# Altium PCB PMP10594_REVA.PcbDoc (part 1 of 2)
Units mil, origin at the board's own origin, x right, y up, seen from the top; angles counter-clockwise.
Board outline 4300 x 2600 mil, 4 copper layers (Top Layer, Signal Layer 1, Signal Layer 2, Bottom Layer), stack 61.2 mil thick; 149 components, 76 nets, 349 pads, 143 vias.
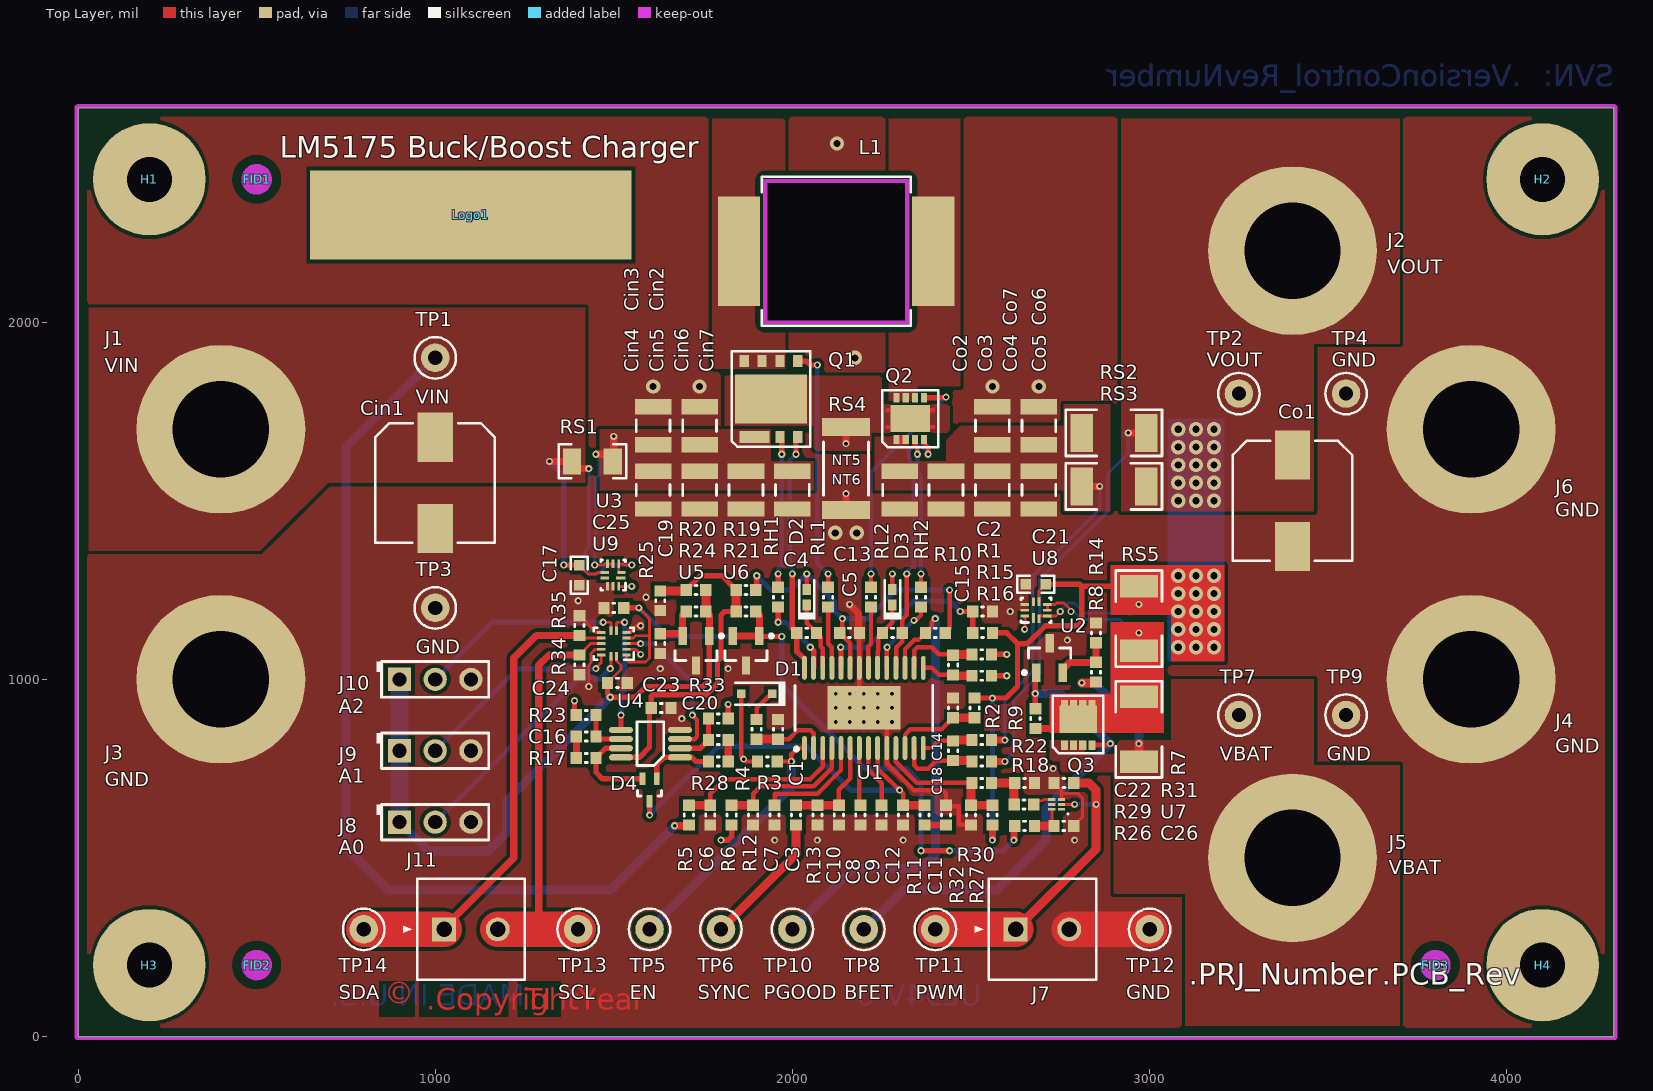
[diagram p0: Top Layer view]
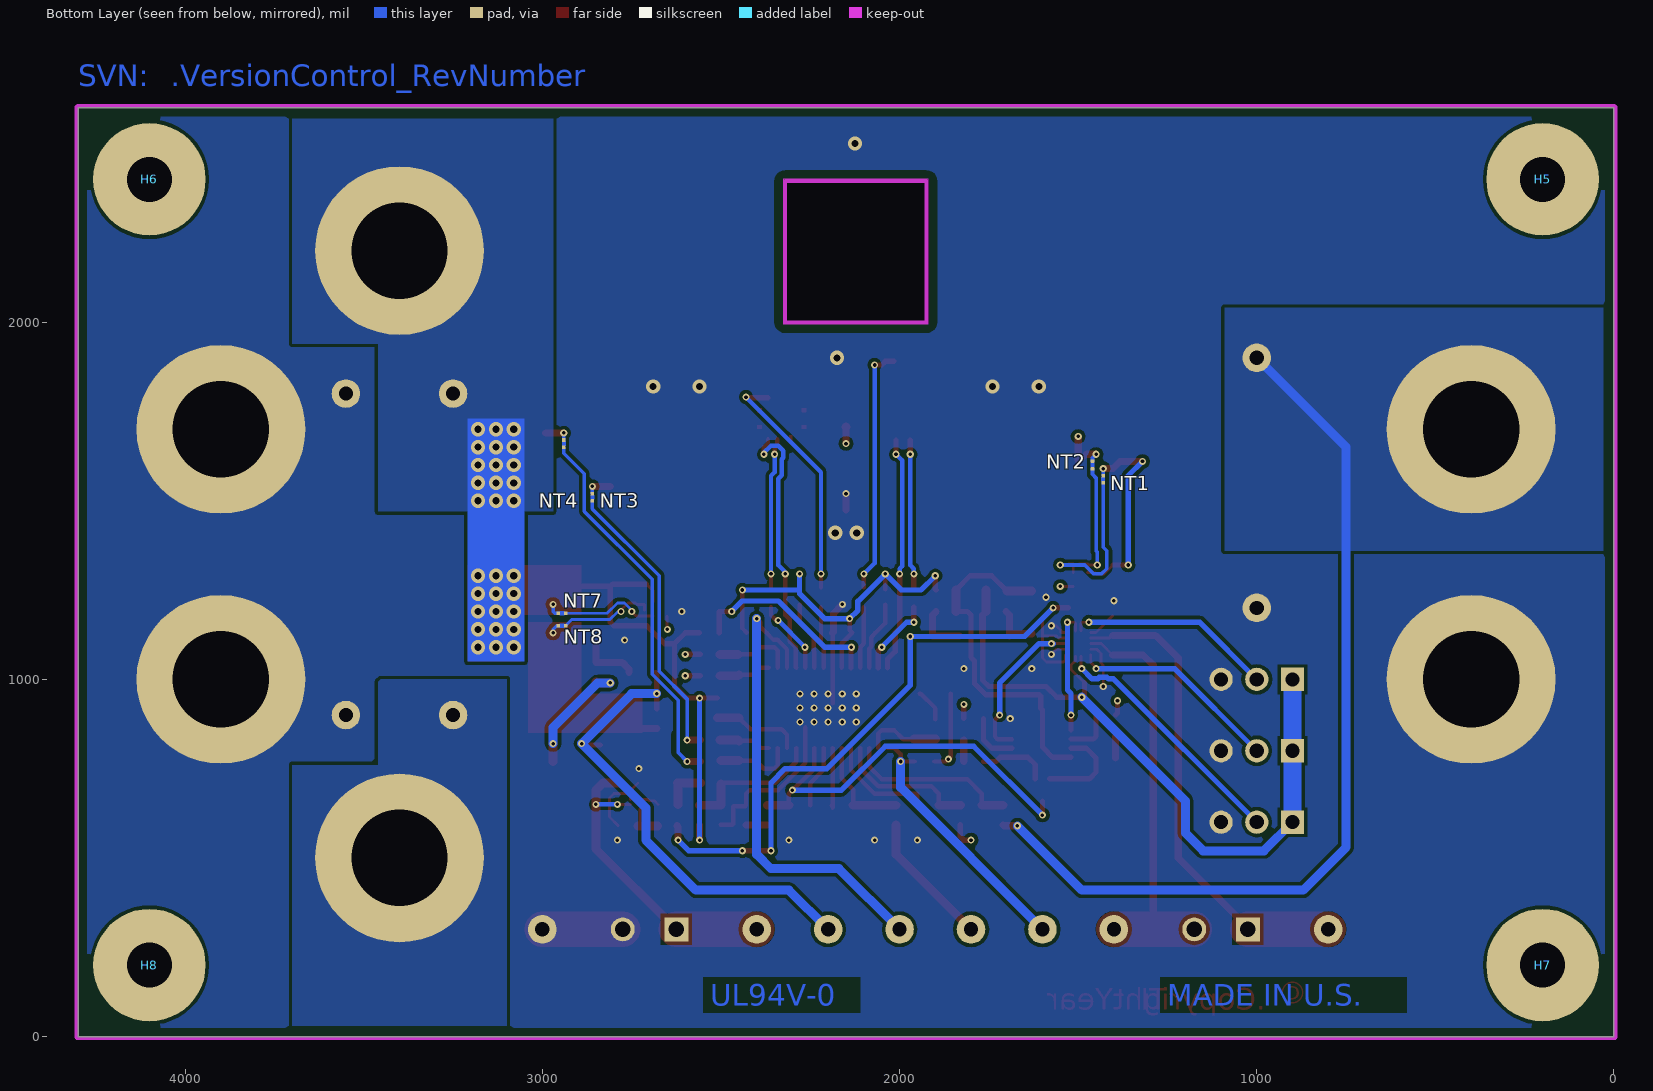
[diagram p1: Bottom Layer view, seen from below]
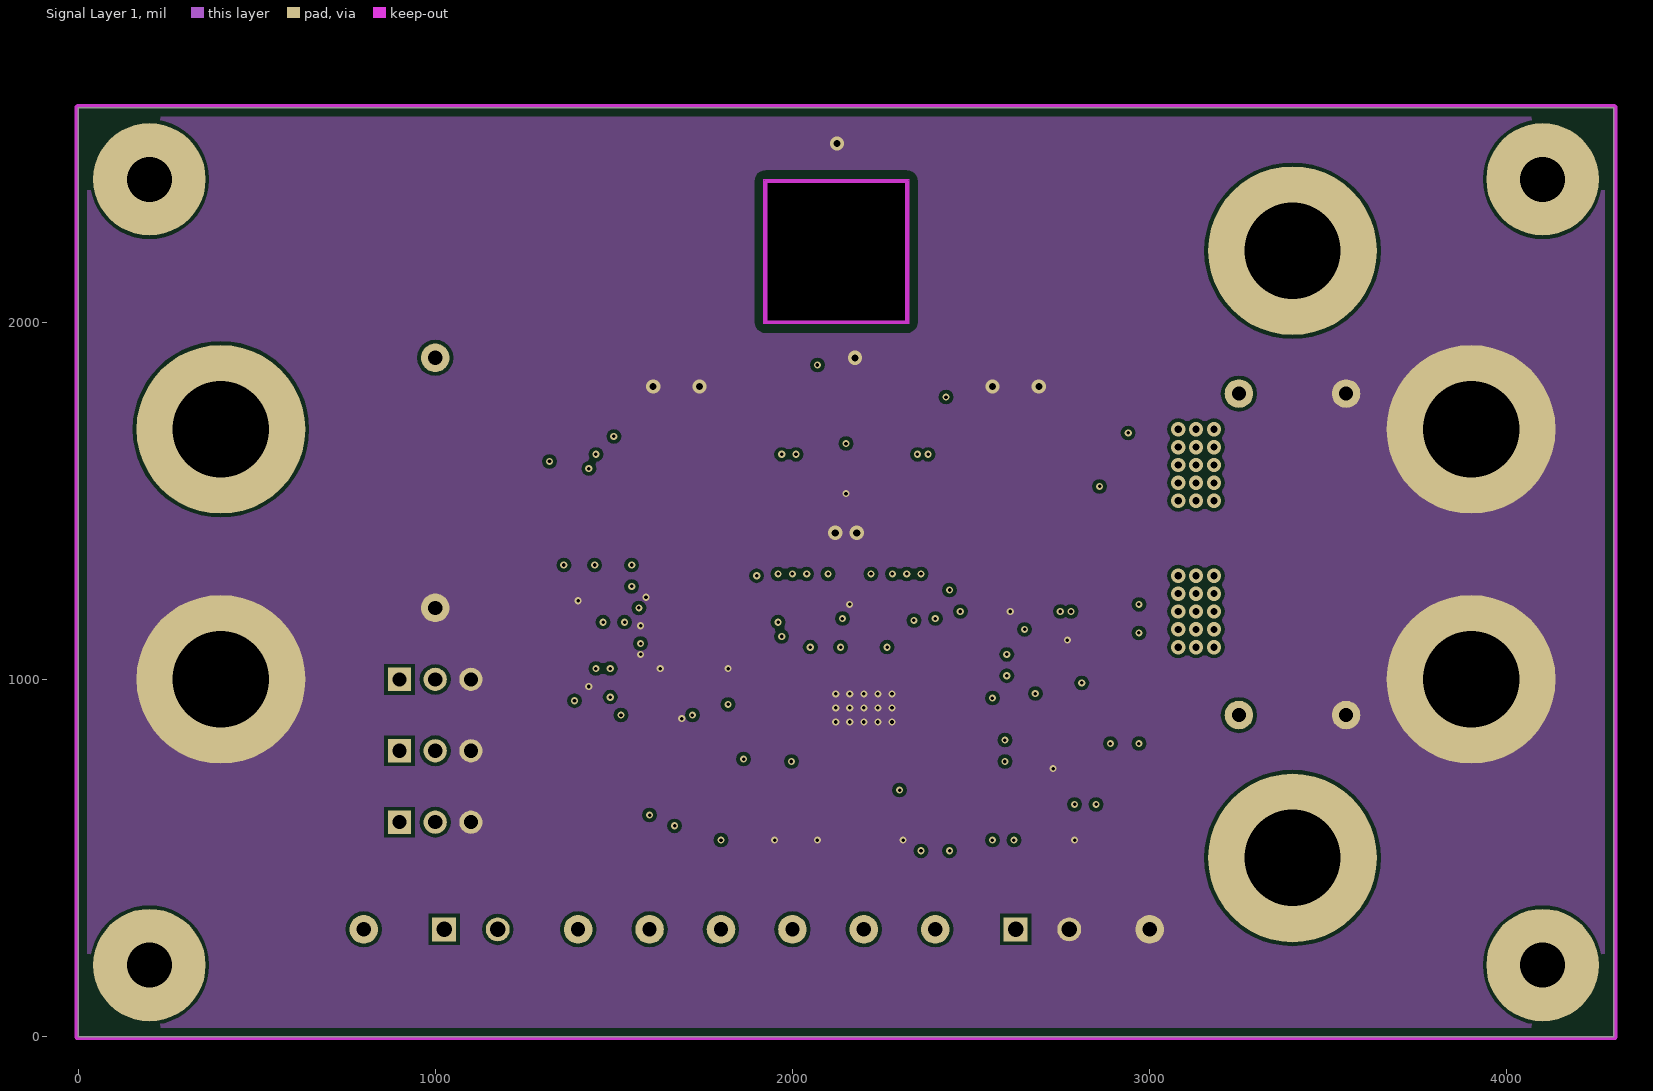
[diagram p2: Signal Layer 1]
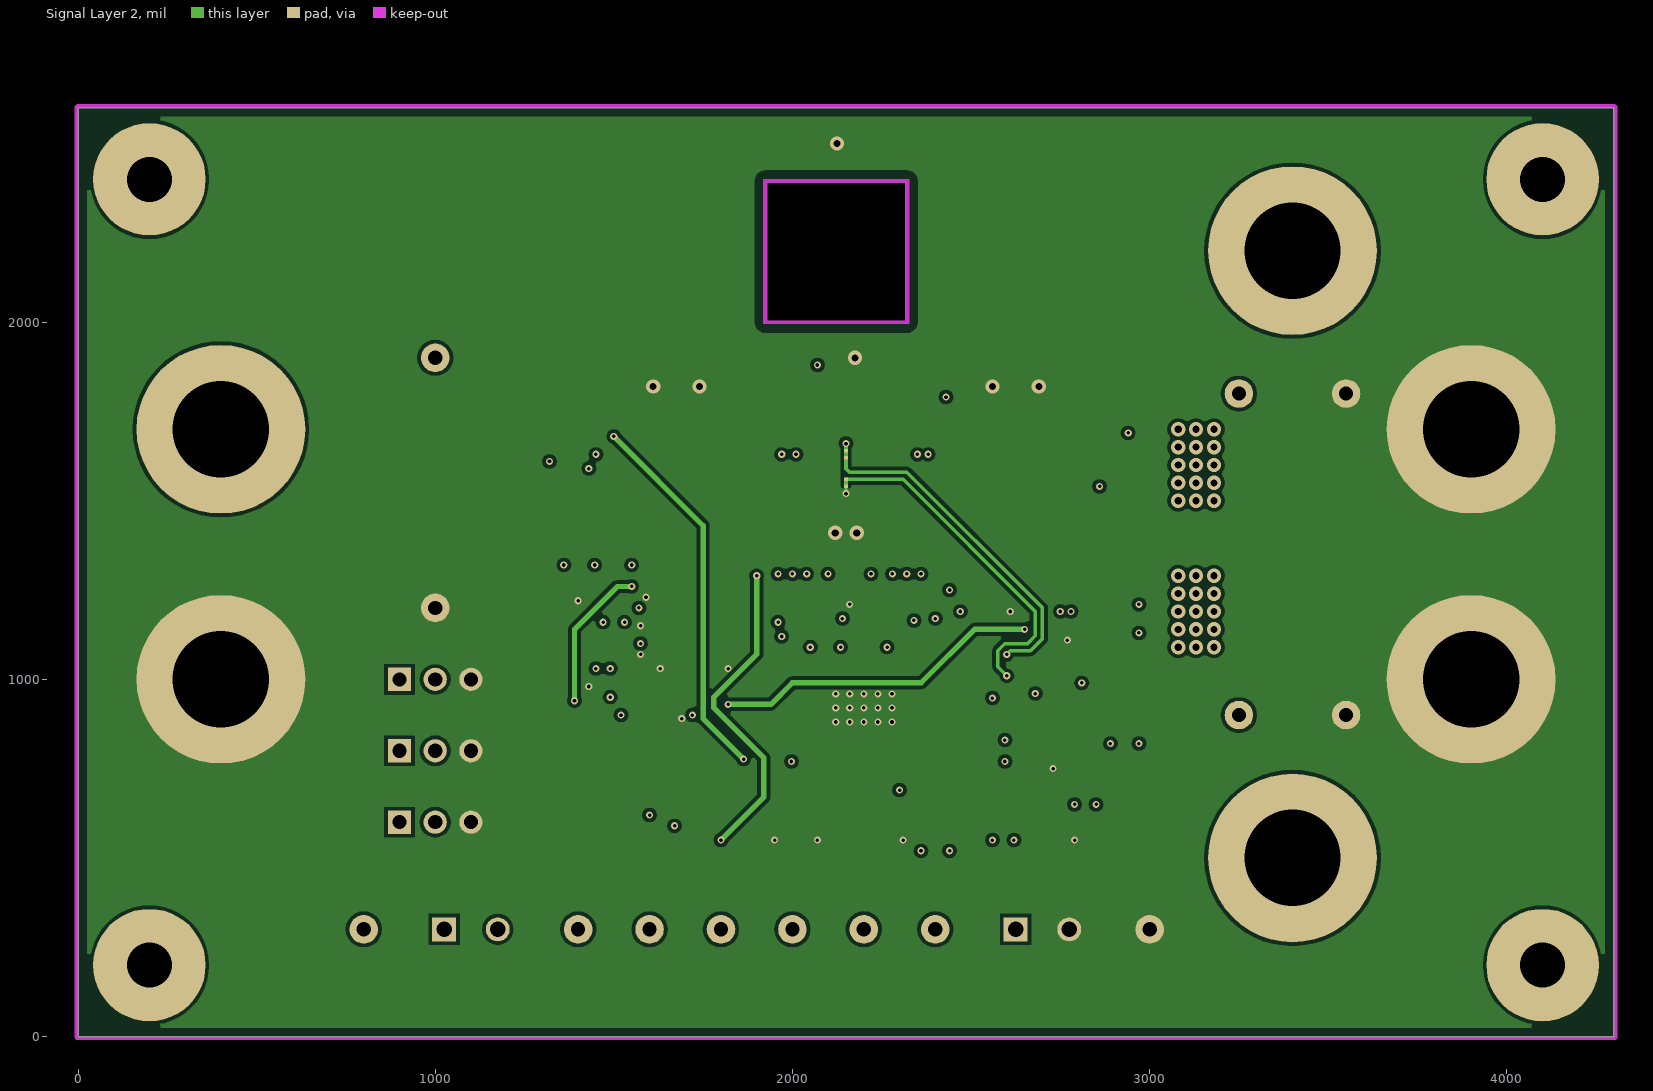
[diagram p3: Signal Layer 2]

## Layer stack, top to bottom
Top Solder: solder mask 0.4, Solder Resist, Dk 3.5
Top Layer: signal copper 2.8
Dielectric1: core 20, FR-4, Dk 4.8
Signal Layer 1: signal copper 1.4
Dielectric 2: prepreg 12.8, Dk 4.2
Signal Layer 2: signal copper 1.4
Dielectric 3: core 20, FR-4, Dk 4.8
Bottom Layer: signal copper 2.8
Bottom Solder: solder mask 0.4, Solder Resist, Dk 3.5

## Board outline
0,0 0,2600 4300,2600 4300,0
cut-out: 1920,2400 2325,2400 2325,1995 1920,1995

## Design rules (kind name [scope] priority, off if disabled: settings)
AcuteAngle [All] p1: minimum=4.50000000000000E+0001 checktracksonly=FALSE
AssemblyTestPointUsage [All] p1: valid=2
Clearance Clearance_IHLW [HasFootprint('IHLW-4040CF') vs IsKeepOut] p1: gap=10
Clearance Clearance_Keepouts [((IsTrack Or IsArc) And Not InPoly) And IsFree and IsKeepOut vs ((IsTrack Or IsArc) And Not InPoly) And IsFree and IsKeepOut] p2: gap=0
Clearance Clearance_BoardEdge_MountingHoles [OnCopper and InComponentClass('Mounting Holes') vs IsKeepOut] p3: gap=40
Clearance Clearance_BoardEdge_Poly [OnCopper and InPoly vs IsKeepOut] p4: gap=25
Clearance Clearance_BoardEdge [OnCopper and Not InComponentClass('Logo') and not InComponentClass('FiducialMark') and not InRegion(1000,500,4000,800) and Not IsKeepout vs IsKeepOut] p5: gap=75
Clearance Clearance_Poly [InPolygon] p6: gap=10
Clearance [All] p7: gap=5.91
ComponentClearance ComponentClearance_Shunt [InComponentClass('Header') vs InComponentClass('Shunt')] p1: gap=0 collisioncheckmode=3 verticalgap=0 showdistances=FALSE
ComponentClearance ComponentClearance_MountingHoles_FiducialMarks [InComponentClass('Mounting Holes') vs InComponentClass('FiducialMark')] p2: gap=50 collisioncheckmode=3 verticalgap=10 showdistances=FALSE
ComponentClearance ComponentClearance_Logo [InComponentClass('Logo')] p3: gap=50 collisioncheckmode=3 verticalgap=10 showdistances=FALSE
ComponentClearance ComponentClearance_ScrewToNut [(HasFootprint('NY PMS 440 0025 PH')) vs (HasFootprint('Keystone_1902C'))] p4: gap=5 collisioncheckmode=3 verticalgap=10 showdistances=FALSE
ComponentClearance ComponentClearance_MountingHoles [InComponentClass('Mounting Holes')] p5: gap=250 collisioncheckmode=3 verticalgap=100000 showdistances=FALSE
ComponentClearance ComponentClearance_SMTtoSMT [IsSMTComponent vs IsSMTComponent] p6: gap=20 collisioncheckmode=3 verticalgap=20 showdistances=FALSE
ComponentClearance ComponentClearance_SmallPassives [HasFootprint('0201*') or HasFootprint('0402*') or HasFootprint('0508') or HasFootprint('0603*') or HasFootprint('0612') or HasFootprint('0805*') or HasFootprint('0815*') or HasFootprint('0830*') or HasFootprint('1206*') or HasFootprint('1210*') or HasFootprint('1808*') or HasFootprint('1812*') or HasFootprint('1825*') or HasFootprint('2010*') or HasFootprint('2220*') or HasFootprint('2225*') or HasFootprint('2512*') or HasFootprint('2728*') or HasFootprint('3518*') or HasFootprint('Net-Tie_10mil') vs HasFootprint('0201*') or HasFootprint('0402*') or HasFootprint('0508') or HasFootprint('0603*') or HasFootprint('0612') or HasFootprint('0805*') or HasFootprint('0815*') or HasFootprint('0830*') or HasFootprint('1206*') or HasFootprint('1210*') or HasFootprint('1808*') or HasFootprint('1812*') or HasFootprint('1825*') or HasFootprint('2010*') or HasFootprint('2220*') or HasFootprint('2225*') or HasFootprint('2512*') or HasFootprint('2728*') or HasFootprint('3518*') or HasFootprint('Net-Tie_10mil')] p7: gap=20 collisioncheckmode=3 verticalgap=10 showdistances=FALSE
ComponentClearance ComponentClearance_THtoSMT [IsThruComponent vs IsSMTComponent] p8: gap=50 collisioncheckmode=3 verticalgap=30 showdistances=FALSE
ComponentClearance ComponentClearance_THtoTH [IsThruComponent vs IsThruComponent] p9: gap=100 collisioncheckmode=3 verticalgap=30 showdistances=FALSE
ComponentClearance [All] p10: gap=40 collisioncheckmode=3 verticalgap=10 showdistances=FALSE
DiffPairsRouting [All] p1: maxlimit=100 minlimit=10 mostfreqgap=10 toplayer_minwidth=7.5 toplayer_maxwidth=20 toplayer_prefwidth=15 midlayer1_minwidth=7.5 midlayer1_maxwidth=20 midlayer1_prefwidth=15 midlayer2_minwidth=7.5 midlayer2_maxwidth=20 midlayer2_prefwidth=15 bottomlayer_minwidth=7.5 bottomlayer_maxwidth=20 bottomlayer_prefwidth=15 maxuncoupledlength=1000
FabricationTestPointUsage TestPointUsage [All] p1: valid=2 allowmultiple=FALSE
FabricationTestpoint Testpoint [All] p1: side=3 testpointundercomponent=TRUE minsize=40 maxsize=100 preferedsize=60 minholesize=0 maxholesize=40 preferedholesize=32 testpointgrid=1 allowsidetop=TRUE allowsidebottom=TRUE usegrid=TRUE gridtolerance=0.01
FanoutControl Fanout_LCC [IsLCC] p1: bgadir=Out bgaviamode=Centered fanoutstyle=Auto fanoutdirection=Alternating viagrid=1 // Fanout_LCC (Default Rule)
FanoutControl Fanout_BGA [IsBGA] p2: bgadir=Out bgaviamode=Centered fanoutstyle=Auto fanoutdirection=Alternating viagrid=1 // Fanout_BGA (Default Rule)
FanoutControl Fanout_Default [All] p4: bgadir=Out bgaviamode=Centered fanoutstyle=Auto fanoutdirection=Alternating viagrid=1 // Fanout_Default (Default Rule)
FanoutControl Fanout_Small [(CompPinCount < 5)] p5: bgadir=Out bgaviamode=Centered fanoutstyle=Auto fanoutdirection=OutThenIn viagrid=1 // Fanout_Small (Default Rule)
HoleSize [All] p1: absolutevalues=TRUE maxlimit=271 minlimit=8 maxpercent=80.000 minpercent=20.000
MinimumAnnularRing MinimumAnnularRing_ThermalPadVias [IsVia and InAnyComponent] p1: minimumring=5
MinimumAnnularRing [All] p2: minimumring=5
MinimumSolderMaskSliver MinimumSolderMaskSliver_Logo [InComponentClass('Logo') vs InComponentClass('Logo')] p1: minsoldermaskwidth=0.7
MinimumSolderMaskSliver [All] p2: minsoldermaskwidth=2.95
PlaneConnect [All] p1: planeconnectstyle=Direct reliefexpansion=10 reliefentries=4 reliefconductorwidth=10 reliefairgap=10
PolygonConnect [All] p1: connectstyle=Direct reliefconductorwidth=10 reliefentries=4 polygonreliefangle="90 Angle" airgapwidth=10
RoutingVias ThermalPadVias [IsVia and InAnyComponent] p1: holewidth=7.87 width=19.68 viastyle="Through Hole" minholewidth=7.87 minwidth=19.68 maxholewidth=12.99 maxwidth=23.62
RoutingVias [All] p2: holewidth=16 width=34 viastyle="Through Hole" minholewidth=7.87 minwidth=20 maxholewidth=40 maxwidth=65
SilkToBoardRegionClearance [Not ((IsComment or IsDesignator) And (Hide <> 'False')) and not InRegion(1000,500,4000,800)] p1:
SilkToSilkClearance SilkToSilkClearance_Pb-FreeLogo [(HasFootprint('Pb-Free_Overlay_Medium') OR HasFootprint('Pb-Free_Overlay_Small')) vs (HasFootprint('Pb-Free_Overlay_Medium') OR HasFootprint('Pb-Free_Overlay_Small'))] p1: silktosilkclearance=0
SilkToSilkClearance [All] p2: silktosilkclearance=5
SilkToSolderMaskClearance "Silk to Solder Mask Opening" [All] p1: minsilkscreentomaskgap=1 clearancetoexposedcopper=FALSE
SolderMaskExpansion [All] p1: expansion=1.97
UnpouredPolygon [All] p1: allowunpoured=FALSE
Width [All] p1: maxlimit=100 minlimit=6 preferedwidth=10 checkconnectedcopper=TRUE
14 further rules are at their usual default settings.

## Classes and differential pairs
component class "Mounting Holes": H1 H2 H3 H4
component class Logo: Logo1
component class PMP10594_REVA_Sh2: FID1 FID2 FID3 H1 H2 H3 H4 H5 H6 H7 H8 Logo1 ZZ1 ZZ2 ZZ3
component class FiducialMark: FID1 FID2 FID3
component class AssemblyNote: ZZ1 ZZ2 ZZ3
component class Header: J8 J9 J10
component class PMP10594_REVA_Sh1: C1 C2 C3 C4 C5 C6 C7 C8 C9 C10 C11 C12 C13 C14 C15 C16 C17 C18 C19 C20 C21 C22 C23 C24 C25 C26 Cin1 Cin2 Cin3 Cin4 Cin5 Cin6 Cin7 Co1 Co2 Co3 Co4 Co5 Co6 Co7 D1 D2 D3 D4 J1 J2 J3 J4 J5 J6 J7 J8 J9 J10 J11 L1 NT1 NT2 NT3 NT4 NT5 NT6 NT7 NT8 Q1 Q2 Q3 R1 R2 R3 R4 R5 R6 R7 R8 R9 R10 R11 R12 R13 R14 R15 R16 R17 R18 R19 R20 R21 R22 R23 R24 R25 R26 R27 R28 R29 R30 R31 R32 R33 R34 R35 RH1 RH2 RL1 RL2 RS1 RS2 RS3 RS4 RS5 TP1 TP2 TP3 TP4 TP5 TP6 TP7 TP8 TP9 TP10 TP11 TP12 TP13 TP14 U1 U2 U3 U4 U5 U6 U7 U8 U9
differential pair ISNS_OUT: +ISNS_OUT_P -ISNS_OUT_N
differential pair HDRV2: +HDRV2_P -HDRV2_N
differential pair HDRV1: +HDRV1_P -HDRV1_N
differential pair CS: +CS_P -CS_N
differential pair VIN: +ISNS_IN_P -ISNS_IN_N
differential pair VOUT: +ISNS_CHG_P -ISNS_CHG_N

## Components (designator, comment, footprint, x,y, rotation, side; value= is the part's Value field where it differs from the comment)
C1 "C1608X7R1H224K080AB" 0603L 1960,860 r90 top
C2 "C1608X7R1H224K080AB" 0603L 2532.44,1190 r0 top
C3 "CGA3E2NP01H101J080AA" 0603L 2010,620 r90 top
C4 "06033C104JAT2A" 0603L 2040,1130 r180 top
C5 "GRM188R71C105KA12D" 0603L 2160,1130 r0 top
C6 "GRM1885C1H101JA01D" 0603L 1770,620 r90 top
C7 "CRCW06030000Z0EA" 0603L 1950,620 r90 top
C8 "GRM1885C1H101JA01D" 0603L 2190,620 r270 top
C9 "GRM188R71H473KA61D" 0603L 2250,620 r270 top
C10 "DNP" 0603L 2130,620 r90 top
C11 "GRM188R71H223KA01D" 0603L 2430,620 r90 top
C12 "GRM1885C1H221JA01D" 0603L 2310,620 r270 top
C13 "06033C104JAT2A" 0603L 2280,1130 r180 top
C14 "GRM1885C1H101JA01D" 0603L 2450,920 r90 top
C15 "DNP" 0603L 2450,1040 r270 top
C16 "06033C104JAT2A" 0603L 1422.6,840 r0 top
C17 "C1608X7R1H224K080AB" 0603_HV 1402.92,1291.55 r270 top
C18 "DNP" 0603L 2450,800 r90 top
C19 "06033C104JAT2A" 0603L 1630,1220 r270 top
C20 "06033C104JAT2A" 0603L 1792.6,830 r180 top
C21 "C1608X7R1H224K080AB" 0603_HV 2680.92,1266.31 r180 top
C22 "06033C104JAT2A" 0603L 2650,710 r0 top
C23 "06033C104JAT2A" 0603L 1632.6,919.69 r0 top
C24 "GRM188R71H102KA01D" 0603L 1510,990 r0 top
C25 "GRM188R71H102KA01D" 0603L 1500,1200 r0 top
C26 "GRM188R71H102KA01D" 0603L 2759.87,590 r0 top
Cin1 "EEHZC1H680P" SM_RADIAL_8MM 1000,1550 r270 top
Cin2 "GRM32ER71H106KA12L" 1210L 1740,1710 r90 top
Cin3 "GRM32ER71H106KA12L" 1210L 1610,1710 r90 top
Cin4 "GRM32ER71H106KA12L" 1210L 1610,1530 r270 top
Cin5 "GRM32ER71H106KA12L" 1210L 1740,1530 r270 top
Cin6 "GRM32ER71H106KA12L" 1210L 1870,1530 r270 top
Cin7 "GRM32ER71H106KA12L" 1210L 2000,1530 r270 top
Co1 "EEHZC1H680P" SM_RADIAL_8MM 3400,1500 r270 top
Co2 "GRM32ER71H106KA12L" 1210L 2300,1530 r270 top
Co3 "GRM32ER71H106KA12L" 1210L 2430,1530 r270 top
Co4 "GRM32ER71H106KA12L" 1210L 2560,1530 r270 top
Co5 "GRM32ER71H106KA12L" 1210L 2690,1530 r270 top
Co6 "GRM32ER71H106KA12L" 1210L 2690,1710 r90 top
Co7 "GRM32ER71H106KA12L" 1210L 2560,1710 r90 top
D1 "BAT54HT1G" sod-323 1900,960 r180 top
D2 "BAS516,115" SOD-523 2040,1230 r90 top
D3 "BAS516,115" SOD-523 2280,1230 r90 top
D4 "BAT54CT-7-F" SOT-523 1600,690 r270 top
FID1 "Fiducial" Fiducial10-20 500,2400 r0 top
FID2 "Fiducial" Fiducial10-20 500,200 r0 top
FID3 "Fiducial" Fiducial10-20 3800,200 r0 top
H1 "NY PMS 440 0025 PH" "NY PMS 440 0025 PH" 200,2400 r0 top locked
H2 "NY PMS 440 0025 PH" "NY PMS 440 0025 PH" 4100,2400 r0 top locked
H3 "NY PMS 440 0025 PH" "NY PMS 440 0025 PH" 200,200 r0 top locked
H4 "NY PMS 440 0025 PH" "NY PMS 440 0025 PH" 4100,200 r0 top locked
H5 "1902C" Keystone_1902C 200,2400 r180 bottom locked
H6 "1902C" Keystone_1902C 4100,2400 r180 bottom locked
H7 "1902C" Keystone_1902C 200,200 r180 bottom locked
H8 "1902C" Keystone_1902C 4100,200 r180 bottom locked
J1 "VIN" Johnson_108-0740-001 400,1700 r0 top
J2 "VOUT" Johnson_108-0740-001 3400,2200 r0 top
J3 "GND" Johnson_108-0740-001 400,1000 r0 top
J4 "GND" Johnson_108-0740-001 3900,1000 r0 top
J5 "VBAT" Johnson_108-0740-001 3400,500 r0 top
J6 "GND" Johnson_108-0740-001 3900,1700 r0 top
J7 "1727010" PhoenixConact_1727010 2700,300 r0 top
J8 "A0" TE_5-146278-3 1000,600 r0 top
J9 "A1" TE_5-146278-3 1000,800 r0 top
J10 "A2" TE_5-146278-3 1000,1000 r0 top
J11 "1727010" PhoenixConact_1727010 1100,300 r0 top
L1 "IHLW4040CFER1R5M11" IHLW-4040CF 2122.5,2198.5 r0 top
Logo1 "Texas Instruments" TI_Stacked_SolderMask_Small 1100,2300 r0 top
NT1 "Net-Tie" Net-Tie_10mil#1 1430,1560 r270 bottom net-tie
NT2 "Net-Tie" Net-Tie_10mil#1 1460,1600 r90 bottom net-tie
NT3 "Net-Tie" Net-Tie_10mil#1 2860,1510 r90 bottom net-tie
NT4 "Net-Tie" Net-Tie_10mil#1 2940,1660 r90 bottom net-tie
NT5 "Net-Tie" Net-Tie_10mil#2 2150,1630 r270 top net-tie
NT6 "Net-Tie" Net-Tie_10mil#2 2150,1550 r90 top net-tie
NT7 "Net-Tie" Net-Tie_10mil#1 2945,1185 r0 bottom net-tie
NT8 "Net-Tie" Net-Tie_10mil#1 2945,1150 r0 bottom net-tie
Q1 "CSD87353Q5D" TRANS_NexFET_Q5D 1940,1785 r90 top
Q2 "CSD87330Q3D" TRANS_NexFET_Q3D 2330,1730 r90 top
Q3 "CSD25402Q3A" TRANS_NexFET_Q3A 2800,880 r90 top
R1 "CRCW060310R0JNEA" 0603L 2532.44,1130 r0 top
R2 "CRCW06031K00FKEA" 0603L 2510,920 r90 top
R3 "CRCW0603100KJNEA" 0603L 1930,770 r180 top
R4 "CRCW060310R0JNEA" 0603L 1900,860 r90 top
R5 "CRCW060310R0JNEA" 0603L 1710,620 r90 top
R6 "DNP" 0603L 1830,620 r270 top
R7 "CRCW2010100RJNEF" 2010 2970,860 r270 top
R8 "CRCW060334K8FKEA" 0603L 2850,1020 r270 top
R9 "CRCW060310K0JNEA" 0603L 2680,890 r90 top
R10 "CRCW060320K0JNEA" 0603L 2400,1130 r0 top
R11 "CRCW06033K01FKEA" 0603L 2370,620 r90 top
R12 "CRCW0603200KFKEA" 0603L 1890,620 r90 top
R13 "CRCW060360K4FKEA" 0603L 2070,620 r90 top
R14 "CRCW060324K9FKEA" 0603L 2850,1130 r270 top
R15 "CRCW06030000Z0EA" 0603L 2530,1070 r0 top
R16 "CRCW06030000Z0EA" 0603L 2530,1010 r0 top
R17 "CRCW060310R0JNEA" 0603L 1422.6,780 r180 top
R18 "CRCW06030000Z0EA" 0603L 2530,770 r180 top
R19 "CRCW060310R0JNEA" 0603L 1870,1250 r0 top
R20 "CRCW06033K30JNEA" 0603L 1730,1250 r0 top
R21 "CRCW06033K30JNEA" 0603L 1870,1190 r0 top
R22 "CRCW06030000Z0EA" 0603L 2530,830 r180 top
R23 "CRCW060310K0FKEA" 0603L 1422.6,900 r180 top
R24 "CRCW06038K06FKEA" 0603L 1730,1190 r0 top
R25 "CRCW060324K9FKEA" 0603L 1630,1100 r90 top
R26 "CRCW060310R0JNEA" 0603L 2649.87,590 r180 top
R27 "CRCW06039K53FKEA" 0603L 2560,620 r270 top
R28 "CRCW060310R0JNEA" 0603L 1792.6,770 r0 top
R29 "CRCW06031K00FKEA" 0603L 2648.35,649.69 r0 top
R30 "CRCW060310K0FKEA" 0603L 2530,710 r180 top
R31 "CRCW0603100KJNEA" 0603L 2760,710 r0 top
R32 "CRCW06031K00FKEA" 0603L 2500,620 r90 top
R33 "CRCW060310K0FKEA" 0603L 1792.6,890 r0 top
R34 "CRCW0603100KJNEA" 0603L 1403.62,1040.62 r90 top
R35 "CRCW0603100KJNEA" 0603L 1403.62,1150.62 r270 top
RH1 "CRCW06030000Z0EA" 0603L 1960,1230 r90 top
RH2 "CRCW06030000Z0EA" 0603L 2360,1230 r270 top
RL1 "CRCW06030000Z0EA" 0603L 2100,1230 r90 top
RL2 "CRCW06030000Z0EA" 0603L 2220,1230 r270 top
RS1 "CSNL1206FT2L00" 1206 1440,1610 r0 top
RS2 "PMR50HZPFU5L00" 2010 2900,1690 r0 top
RS3 "PMR50HZPFU5L00" 2010 2900,1540 r0 top
RS4 "CSNL2512FT4L00" 2512 2150,1590 r90 top
RS5 "PMR50HZPFV1L00" 2010 2970,1170 r270 top
TP1 "VIN" Keystone5000 1000,1900 r0 top
TP2 "VOUT" Keystone5000 3250,1800 r0 top
TP3 "GND" Keystone5001 1000,1200 r0 top
TP4 "GND" Keystone5001 3550,1800 r0 top
TP5 "EN" Keystone5002 1600,300 r0 top
TP6 "SYNC" Keystone5002 1800,300 r0 top
TP7 "VBAT" Keystone5000 3250,900 r0 top
TP8 "BFET" Keystone5002 2200,300 r0 top
TP9 "GND" Keystone5001 3550,900 r0 top
TP10 "PGOOD" Keystone5002 2000,300 r0 top
TP11 "PWM" Keystone5000 2400,300 r0 top
TP12 "GND" Keystone5001 3000,300 r0 top
TP13 "SCL" Keystone5002 1400,300 r0 top
TP14 "SDA" Keystone5002 800,300 r0 top
U1 "LM5175PWP" PWP0028F_N 2200,920 r90 top
U2 "LM431ACM3" MF03A_N 2720,1060 r90 top
U3 "INA199A3RSW" RSW0010A 1497.92,1291.55 r180 top
U4 "LM358DGK" DGK0008A_N 1602.6,820 r180 top
U5 "LM431ACM3" MF03A_N 1730,1080 r270 top
U6 "LM431ACM3" MF03A_N 1870,1080 r270 top
U7 "SN74LVC1G34DSF" DSF0006A 2739.87,650 r180 top
U8 "INA199A3RSW" RSW0010A 2682.47,1193.39 r90 top
U9 "TPL0102-100RUCR" RUC0014A 1500,1100 r180 top
ZZ1 "These assemblies are ESD sensitive, ESD precautions shall be observed." AssemblyNote 185,3829.11 r0 top
ZZ2 "These assemblies must be clean and free from flux and all contaminants. Use of no clean flux is not acceptable." AssemblyNote 185,3740.56 r0 top
ZZ3 "These assemblies must comply with workmanship standards IPC-A-610 Class 2, unless otherwise specified." AssemblyNote 185,3652 r0 top

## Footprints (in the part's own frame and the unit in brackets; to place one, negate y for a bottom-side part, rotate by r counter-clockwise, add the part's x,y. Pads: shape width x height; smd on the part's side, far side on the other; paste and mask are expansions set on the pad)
0603_HV [mil] "Ernesto recommended land pattern.  26 mil between pads."
  rect 30x30 smd: 1(-28,0) 2(28,0)
  silkscreen extent -52,-24 52,24, body extent -34,-19 34,19, height 33
0603L [mm] "0603 from SM-752 data"
  rect 0.8x0.85 smd: 1(-0.7,0) 2(0.7,0)
  silkscreen extent -0.07,-0.33 0.07,0.33, body extent -0.87,-0.47 0.87,0.47, height 0.85
1206 [mm] "1206 from SM-752 data"
  rect 1.3x1.85 smd: 1(-1.45,0) 2(1.45,0)
  silkscreen extent -2.4,-1.21 2.4,1.21, body extent -1.7,-0.9 1.7,0.9, height 1.35
1210L [mm] "1210 from SM-752 data"
  rect 1.1x2.6 smd: 1(-1.35,0) 2(1.35,0)
  silkscreen extent -0.4,-1.2 0.4,1.2, body extent -1.7,-1.35 1.7,1.35, height 1.35
2010 [mm] "Chip Capacitor, Body 5.08x2.54mm, IPC Medium Density"
  rect 1.6x2.7 smd: 1(-2.3,0) 2(2.3,0)
  silkscreen extent -3.42,-1.65 3.42,1.65, body extent -2.73,-1.45 2.73,1.45, height 1.66
2512 [mm] "Chip Resistor, Body 6.3x3.2mm, IPC Medium Density"
  rect 1.3x3.4 smd: 1(-2.95,0) 2(2.95,0)
  silkscreen extent -1.9,-1.6 1.9,1.6, body extent -3.22,-1.67 3.22,1.67, height 0.71
AssemblyNote [mil] "Assembly Note"
DGK0008A_N [mm] "TSOP, 8-Leads, Body 3x3mm, Pitch 0.65mm, IPC Medium Density"
  oval 1.7x0.45 smd mask+0.05: 1(-2.1,0.975) 2(-2.1,0.325) 3(-2.1,-0.325) 4(-2.1,-0.975) 5(2.1,-0.975) 6(2.1,-0.325) 7(2.1,0.325) 8(2.1,0.975)
  silkscreen extent -0.95,-1.55 0.95,1.55, body extent -2.45,-1.5 2.45,1.5, height 0.94
DSF0006A [mm] "TI recommended land pattern"
  rect 0.53x0.2 smd paste-0.1 mask+0.038: 1(-0.34,0.35) 2(-0.34,0) 3(-0.34,-0.35) 4(0.34,-0.35) 5(0.34,0) 6(0.34,0.35)
  silkscreen extent -0.85,0.63 -0.75,0.72, body extent -0.52,-0.52 0.52,0.52, height 0.4
Fiducial10-20 [mm]
  round 1 smd mask+0.5: 1(0,0)
  Top Layer keep-out circle w1.178: c0,0 r0.5
IHLW-4040CF [mm] "Vishay Dale IHLW data sheet"
  rect 3x7.8 smd: 1(-6.9,0) 2(6.9,0)
  silkscreen extent -5.3,-5.3 5.3,5.3, body extent -5.1,-5.15 5.1,5.15, height 3.8
Johnson_108-0740-001 [mm] "Banana Jack Uninsulated Standard Type"
  round 12 hole 6.858: 1(0,0)
  body extent -4.77,-5.43 4.75,5.57, height 2.39
Keystone5000 [mil] "For Keystone 500x miniature loop terminals"
  round 80 hole 40: 1(0,0)
  silkscreen extent -58,-58 58,58, body extent -49,-49 49,49, height 182
Keystone5001 [mil] "For Keystone 500x miniature loop terminals"
  round 80 hole 40: 1(0,0)
  silkscreen extent -58,-58 58,58, body extent -49,-49 49,49, height 182
Keystone5002 [mil] "For Keystone 500x miniature loop terminals"
  round 80 hole 40: 1(0,0)
  silkscreen extent -58,-58 58,58, body extent -49,-49 49,49, height 182
Keystone_1902C [mil] "Hex Standoff, 4-40 threaded, nylon"
  body extent -145,-126 146,126, height 501
MF03A_N [mm] "SOT23, 3-Leads, Body 2.9x1.3mm, Pitch 0.95mm, Lead Span 2.4mm, IPC Medium Density"
  rect 1.3x0.6 smd: 1(-1.05,0.95) 2(-1.05,-0.95) 3(1.05,0)
  silkscreen extent -1.17,-1.5 0.7,1.92, body extent -0.7,-1.5 0.7,1.5, height 1.12
Net-Tie_10mil#1 [mil] "10mil net tie, no solder mask opening, no solder paste"
  rect 10x10 smd paste-5 mask-5: 1(-10,0) 2(10,0)
  Top Layer region: -6,5 6,5 6,-5 -6,-5
Net-Tie_10mil#2 [mil] "10mil net tie, no solder mask opening, no solder paste"
  rect 10x10 on Mid2 paste-5 mask-5: 1(-10,0) 2(10,0)
  Signal Layer 2 region: -6,5 6,5 6,-5 -6,-5
"NY PMS 440 0025 PH" [mm] "4-40 nylon screw and mounting hole"
  round 8 hole 3.2: 1(0,0)
  body extent -3.3,-3.3 3.3,3.3, height 2.69
PhoenixConact_1727010 [mm]
  rect 1.7x1.7 hole 1.1: 1(-1.905,0)
  round 1.7 hole 1.1: 2(1.905,0)
  silkscreen extent -4.8,-3.6 3.81,3.6, body extent -3.81,-3.6 3.81,3.7, height 8.52
PWP0028F_N [mm] "TSOP, 28-Leads, Body 9.7x4.4mm, Pitch 0.65mm, Exposed Pad, IPC Medium Density"
  oval 1.7x0.35 smd: 1(-2.85,4.225) 2(-2.85,3.575) 3(-2.85,2.925) 4(-2.85,2.275) 5(-2.85,1.625) 6(-2.85,0.975) 7(-2.85,0.325) 8(-2.85,-0.325) 9(-2.85,-0.975) 10(-2.85,-1.625) 11(-2.85,-2.275) 12(-2.85,-2.925) 13(-2.85,-3.575) 14(-2.85,-4.225) 15(2.85,-4.225) 16(2.85,-3.575) 17(2.85,-2.925) 18(2.85,-2.275) 19(2.85,-1.625) 20(2.85,-0.975) 21(2.85,-0.325) 22(2.85,0.325) 23(2.85,0.975) 24(2.85,1.625) 25(2.85,2.275) 26(2.85,2.925) 27(2.85,3.575) 28(2.85,4.225)
  rect 3.1x5.18 smd: 29(0,0)
  silkscreen extent -3.05,-4.9 1.6,4.92, body extent -3.21,-4.85 3.21,4.85, height 0.98
RSW0010A [mm] "QFN, 10-Leads, Body 1.8x1.4 mm, Pitch 0.4mm, TI Recommended"
  rect 0.7x0.2 smd: 1(-0.55,0.2)
  rect 0.6x0.2 smd: 2(-0.6,-0.2) 6(0.6,-0.2) 7(0.6,0.2)
  rect 0.2x0.6 smd: 3(-0.4,-0.8) 4(0,-0.8) 5(0.4,-0.8) 8(0.4,0.8) 9(0,0.8) 10(-0.4,0.8)
  silkscreen extent -0.88,-1.08 0.88,1.08, body extent -0.73,-0.92 0.72,0.93, height 0.56
RUC0014A [mm] "TI"
  rect 0.6x0.2 smd: 1(-0.9,0.8) 2(-0.9,0.4) 3(-0.9,0) 4(-0.9,-0.4) 5(-0.9,-0.8) 8(0.9,-0.8) 9(0.9,-0.4) 10(0.9,0) 11(0.9,0.4) 12(0.9,0.8)
  rect 0.2x0.6 smd: 6(-0.2,-0.9) 7(0.2,-0.9) 13(0.2,0.9) 14(-0.2,0.9)
  silkscreen extent -1.43,-1.13 1.43,1.15, body extent -1.02,-1.02 1.02,1.02, height 0.41
SM_RADIAL_8MM [mm] "Nichicon 8x10"
  rect 3.5x2.5 smd: 1(-3.25,0) 2(3.25,0)
  silkscreen extent -4.25,-4.25 4.25,4.25, body extent -4.26,-4.26 4.26,4.26, height 10.5
sod-323 [mm] "NXP recommended land pattern"
  rect 0.6x0.6 smd paste-0.05: 1(-1.1,0) 2(1.1,0)
  silkscreen extent -2.06,-0.86 1.53,0.86, body extent -1.3,-0.67 1.3,0.68, height 1.1
SOD-523 [mm] "NXP Semiconductor recommended land pattern, nominal STEP model"
  rect 0.8x0.6 smd paste-0.05: 1(-0.55,0) 2(0.55,0)
  silkscreen extent -1.6,-0.64 1.2,0.63, body extent -0.8,-0.4 0.8,0.4, height 0.72
SOT-523 [mm] "From Diodes Inc datasheet component parameters"
  rect 0.9x0.4 smd: 1(-0.8,0.5) 2(-0.8,-0.5) 3(0.8,0)
  silkscreen extent 0.02,-0.85 0.42,0.85, body extent -0.8,-0.8 0.8,0.8, height 0.79
TE_5-146278-3 [mm] "TE CONNECTIVITY"
  rect 1.65x1.65 hole 1: 1(-2.54,0)
  round 1.65 hole 1: 2(0,0) 3(2.54,0)
  silkscreen extent -4.19,-1.27 3.81,1.27, body extent -3.68,-1.17 3.68,1.17, height 8.13
TI_Stacked_SolderMask_Small [mil]
  rect 900x250 smd paste-125 mask-125: 0(0,0)
TRANS_NexFET_Q3A [mm] "TI"
  rect 0.68x0.5 smd paste-1 mask+0.076: 1(-1.625,0.975) 2(-1.625,0.325) 3(-1.625,-0.325) 4(-1.625,-0.975)
  rect 0.41x0.5 smd paste-1 mask+0.076: 5(1.385,-0.975) 6(1.385,-0.325) 7(1.385,0.325) 8(1.385,0.975)
  rect 1.96x2.65 smd paste-3 mask+0.076: 9(0.205,0)
  Top Layer region: 1,-1.325 1.24,-1.325 1.24,-1.1 1,-1.1
  Top Layer region: 1,1.1 1.24,1.1 1.24,1.325 1,1.325
  silkscreen extent -2.21,-1.8 1.9,1.8, body extent -1.55,-1.62 1.55,1.62, height 0.91
TRANS_NexFET_Q3D [mm] "TI recommended land pattern M0143-01"
  rect 0.65x0.44 smd paste-0.05 mask+0.06: 1(-1.48,0.975) 2(-1.48,0.325) 3(-1.48,-0.325) 4(-1.48,-0.975) 5(1.48,-0.975) 6(1.48,-0.325) 7(1.48,0.325) 8(1.48,0.975)
  rect 1.9x2.8 smd paste-5 mask+0.06: 9(0,0)
  Top Layer region: -0.74,-1.75 -0.44,-1.75 -0.44,-1.4 -0.74,-1.4
  Top Layer region: 0.44,-1.75 0.74,-1.75 0.74,-1.4 0.44,-1.4
  Top Layer region: -0.74,1.4 -0.44,1.4 -0.44,1.75 -0.74,1.75
  Top Layer region: 0.44,1.4 0.74,1.4 0.74,1.75 0.44,1.75
  Top Layer region: -1.805,0.531 -1.156,0.531 -1.156,0.759 -1.805,0.759
  silkscreen extent -2.05,-2 2,2, body extent -1.7,-1.7 1.7,1.7, height 1.42
TRANS_NexFET_Q5D [mm] "TI recommended land pattern (nominal) M0188-01"
  rect 0.85x1.2 smd paste-0.1 mask+0.051: 1(-2.695,1.63) 2(-2.695,0.71)
  rect 0.85x0.65 smd paste-0.1 mask+0.051: 3(-2.695,-0.635) 4(-2.695,-1.905) 5(2.695,-1.905) 6(2.695,-0.635) 7(2.695,0.635) 8(2.695,1.905)
  rect 3.48x5.15 smd paste-2.2 mask+0.051: 9(0,0)
  silkscreen extent -3.4,-2.8 3.4,2.8, body extent -3.05,-2.55 3.05,2.55, height 1.51

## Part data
C1 C2 C17 C21: "CAP, CERM, 0.22uF, 50V, +/-10%, X7R, 0603"
C3 C6 C14: "CAP, CERM, 100pF, 50V, +/-5%, C0G/NP0, 0603"
C4 C13 C16 C19 C20 C22 C23: "CAP, CERM, 0.1 µF, 25 V, +/- 5%, X7R, 0603"
C5: "CAP, CERM, 1uF, 16V, +/-10%, X7R, 0603"
C7: "RES, 0, 5%, 0.1 W, 0603"
C8: "CAP, CERM, 100 pF, 50 V, +/- 5%, C0G/NP0, 0603"
C9: "CAP, CERM, 0.047 µF, 50 V, +/- 10%, X7R, 0603"
C10 C15 C18: library part GRM1885C1H101JA01D, "CAP, CERM, 100pF, 50V, +/-5%, C0G/NP0, 0603"
C11: "CAP, CERM, 0.022 µF, 50 V, +/- 10%, X7R, 0603"
C12: "CAP, CERM, 220 pF, 50 V, +/- 5%, C0G/NP0, 0603"
C24 C25 C26: "CAP, CERM, 1000 pF, 50 V, +/- 10%, X7R, 0603"
Cin1 Co1: "CAP, AL, 68 µF, 50 V, +/- 20%, 30 ohm, SMD"
Cin2 Cin3 Cin4 Cin5 Cin6 Cin7: "CAP, CERM, 10uF, 50V, +/-10%, X7R, 1210"
Co2 Co3 Co4 Co5 Co6 Co7: "CAP, CERM, 10 µF, 50 V, +/- 10%, X7R, 1210"
D1: "Diode, Schottky, 30V, 0.2A, SOD-323"
D2 D3: "Diode, Switching, 100V, 0.25A, SOD-523"
D4: "Diode, Schottky, 30 V, 0.2 A, SOT-523"
FID1 FID2 FID3: "Fiducial mark.  There is nothing to buy or mount."
H1 H2 H3 H4: "Machine Screw, Round, #4-40 x 1/4, Nylon, Philips panhead"
H5 H6 H7 H8: "Standoff, Hex, 0.5\"L #4-40 Nylon"
J1 J2 J3 J4 J5 J6: library part 108-0740-001, "Standard Banana Jack, Uninsulated, 15A"
J7 J11: "Conn Term Block, 2POS, 3.81mm PCB"
J8 J9 J10: library part 5-146278-3, "Header, 100mil, 3x1, Tin, TH"
L1: "Inductor, Shielded, Powdered Iron, 1.5 µH, 14.5 A, 0.0044 ohm, SMD, Winged Terminal"
Logo1: library part TI_Logo, "Texas Instrument Corporate Signature"
NT1 NT2 NT3 NT4 NT5 NT6 NT7 NT8: "Single point connection between nets."
Q2: "MOSFET, N/P-CH, 30 V, 20 A, 3.4x1.4x3.4mm"
Q3: "MOSFET, P-CH, -20 V, -15 A, SON 3.3x3.3mm"
R1 R4 R5 R17 R19 R26 R28: "RES, 10, 5%, 0.1 W, 0603"
R2 R29 R32: "RES, 1.00 k, 1%, 0.1 W, 0603"
R3 R31 R34 R35: "RES, 100 k, 5%, 0.1 W, 0603"
R6: library part CRCW06030000Z0EA, "RES, 0, 5%, 0.1 W, 0603"
R7: "RES, 100, 5%, 0.75 W, 2010"
R8: "RES, 34.8 k, 1%, 0.1 W, 0603"
R9: "RES, 10 k, 5%, 0.1 W, 0603"
R10: "RES, 20 k, 5%, 0.1 W, 0603"
R11: "RES, 3.01 k, 1%, 0.1 W, 0603"
R12: "RES, 200 k, 1%, 0.1 W, 0603"
R13: "RES, 60.4 k, 1%, 0.1 W, 0603"
R14 R25: "RES, 24.9 k, 1%, 0.1 W, 0603"
R15 R16 R18 R22 RH1 RH2 RL1 RL2: "RES, 0 ohm, 5%, 0.1W, 0603"
R20 R21: "RES, 3.3 k, 5%, 0.1 W, 0603"
R23 R30 R33: "RES, 10.0 k, 1%, 0.1 W, 0603"
R24: "RES, 8.06 k, 1%, 0.1 W, 0603"
R27: "RES, 9.53 k, 1%, 0.1 W, 0603"
RS1: "RES, 0.002, 1%, 1 W, 1206"
RS2 RS3: "RES, 0.005, 1%, 1 W, 2010"
RS4: "RES, 0.004, 1%, 2 W, 2512"
RS5: "RES, 0.001, 1%, 1 W, 2010"
TP1 TP2 TP7 TP11: library part 5000, "Test Point, TH, Miniature, Red"
TP3 TP4 TP9 TP12: library part 5001, "Test Point, TH, Miniature, Black"
TP5 TP6 TP8 TP10 TP13 TP14: library part 5002, "Test Point, Miniature, White, TH"
U1: "42V Wide VIN 4-Switch Synchronous Buck-Boost Controller, PWP0028F"
U2 U5 U6: "Adjustable Precision Zener Shunt Regulator, 3-pin SOT-23"
U3 U8: "Voltage Output, High or Low Side Measurement, Bi-Directional Zerø-Drift Series Current-Shunt Monitor,  RSW0010A"
U4: "Low Power Dual Op Amp"
U7: "SINGLE BUFFER GATE, DSF0006A"
U9: "256-TAPS DUAL CHANNEL DIGITAL POTENTIOMETER WITH NON-VOLATILE MEMORY, RUC0014A"
ZZ1 ZZ2 ZZ3: library part AssemblyNote

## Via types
v1: diameter 20, hole 10, Top Layer to Bottom Layer, 105 vias
v2: diameter 40, hole 20, Top Layer to Bottom Layer, 38 vias

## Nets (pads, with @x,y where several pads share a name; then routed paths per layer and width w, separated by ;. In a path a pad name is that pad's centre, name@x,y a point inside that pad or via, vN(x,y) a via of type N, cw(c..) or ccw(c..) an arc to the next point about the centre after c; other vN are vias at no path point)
A0: J8.2 U9.13 | length 707
  Top Layer w7.88: v1(1490,1030) 1492.13,1032.13 U9.13@1492.13,1064.57
  Bottom Layer w15: J8.2@1000,600 1401.17,1001.17 1415.28,1001.17 1419.49,1005.37 1440.51,1005.37 1444.72,1001.17 1461.17,1001.17 v1(1490,1030)
A1: J9.2 U9.12 | length 589.8
  Top Layer w7.88: v1(1450,1030) 1450,1032.01 1464.57,1046.58 U9.12@1464.57,1068.5
  Bottom Layer w15: J9.2@1000,800 1230,1030 v1(1450,1030)
A2: J10.2 U9.7 | length 581.7
  Top Layer w7.88: v1(1470,1160) 1490,1160 1492.13,1157.87 U9.7@1492.13,1135.43
  Bottom Layer w15: J10.2@1000,1000 1160,1160 v1(1470,1160)
BIAS: C2.1 R1.1 U1.24 | length 553.8
  Top Layer w15: v1(2135,1090) 2136.02,1088.98 U1.24@2136.02,1032.2 ; v1(2470,1190) C2.1@2504.88,1190 R1.1@2504.88,1130
  Bottom Layer w15: v1(2135,1090) 2210,1090 2339.33,1219.33 2440.67,1219.33 v1(2470,1190)
BOOT1: C4.1 D2.1 U1.26 | length 194.7
  Top Layer w12.5: D2.1@2040,1208.35 2040,1157.56 C4.1@2067.56,1130 2079.63,1117.93 2079.63,1091.56 2084.84,1086.34 U1.26@2084.84,1032.2
BOOT2: C13.2 D3.1 U1.20 | length 193.4
  Top Layer w12.5: U1.20@2238.39,1032.2 2238.39,1078.39 2240.37,1080.37 2240.37,1117.93 C13.2@2252.44,1130 2252.44,1132.44 2280,1160 D3.1@2280,1208.35
COMP: C12.1 D4.3 R11.2 U1.9 | length 1119.7
  Top Layer w12.5: U1.9@2238.39,807.8 2238.39,750 2310,680 C12.1@2310,647.56
  Top Layer w15: v1(1600,620) D4.3@1600,658.5
  Top Layer w25: C12.1@2310,647.56 R11.2@2370,647.56
  Bottom Layer w15: v1(1600,620) 1792.76,812.76 2040,812.76 2162.98,689.77 v1(2300,689.77)
CS_N: NT6.2 R16.2 | length 996.7
  Top Layer w15: R16.2@2557.56,1010 v1(2600,1010)
  Signal Layer 2 w10: NT6.2@2150,1560 2310,1560 2680,1190 2680,1121.93 2658.07,1100 2594.64,1100 2575,1080.36 2575,1035 v1(2600,1010)
CS_P: NT5.2 R15.2 | length 988.4
  Top Layer w15: R15.2@2557.56,1070 v1(2600,1070)
  Signal Layer 2 w10: NT5.2@2150,1620 2150,1590 2160,1580 2320,1580 2700,1200 2700,1113.65 2666.35,1080 2610,1080 v1(2600,1070)
DITH: C7.2 U1.5 | length 305
  Top Layer w12.5: C7.2@1950,647.56 1950,680 2067.43,680 ; 2070,680 2136.02,746.02 U1.5@2136.02,807.8
EN: R3.1 TP5.1 U1.1 | length 733.8
  Top Layer w12.5: R3.1@1957.56,770 1990,770 1997.24,777.24 1997.24,790 2015.04,807.8 U1.1@2033.66,807.8
  Bottom Layer w25: TP5.1@1600,300 1997.24,697.24 v1(1997.24,770)
FB: R27.1 R30.2 R32.2 U1.11 | length 396
  Top Layer w12.5: U1.11@2289.57,807.8 2289.57,769.25 2348.44,710.37 2502.07,710.37 R30.2@2502.44,710
  Top Layer w25: R30.2@2500,707.56 R32.2@2500,647.56 R27.1@2560,647.56
GND: C1.2 C2.2 C5.2 C6.1 C7.1 C8.2 C9.2 C10.1 C11.2 C12.2 C14.2 C17.2 C19.2 C21.2 C22.2 C23.2 C24.2 C25.1 C26.2 Cin1.2 Cin2.2 Cin3.2 Cin4.2 Cin5.2 Cin6.2 Cin7.2 Co1.2 Co2.2 Co3.2 Co4.2 Co5.2 Co6.2 Co7.2 J3.1 J4.1 J6.1 J7.2 J8.3 J9.3 J10.3 NT6.1 R12.1 R13.1 R14.1 R25.1 R31.1 R32.1 R34.1 R35.1 RS4.1 TP3.1 TP4.1 TP9.1 TP12.1 U1.10 U1.22 U1.29 U2.3 U3.8 U3.9 U4.4 U5.3 U6.3 U7.3 U8.8 U8.9 U9.2 U9.5 U9.8 U9.11 | length 1547.3
  Top Layer w7.85: R35.1@1403.62,1178.18 1450.3,1131.5 U9.8@1464.57,1131.5 ; v1(1430,980) 1430,1039.44 1435.96,1045.39 1435.96,1072.33 1447.87,1084.24 1454.24,1084.24 U9.11@1464.57,1084.25 ; U9.2@1535.43,1084.25 1560.75,1084.25 v1(1575,1070) ; U9.5@1535.43,1131.5 1548.42,1131.5 1548.42,1136.61 1561.81,1150 v1(1575,1150) ; R31.1@2732.44,710 2753.25,689.19 2753.25,680 ; U7.3@2753.25,663.78 2753.25,680 ; C26.2@2787.43,590 2812.18,614.75 2812.18,667.82 2800,680 2753.25,680
  Top Layer w12.5: U1.29@2187.2,932.8 U1.22@2187.2,1032.2 2187.2,1129.65 C5.2@2187.56,1130 ; U1.29@2263.98,866.02 U1.10@2263.98,807.8 2263.98,766.02 2340,690 2420,690 2430,680 C11.2@2430,647.56 2432.56,645 2465,645 2465,595 2467.56,592.44 R32.1@2500,592.44
  Top Layer w20: RS4.1@2150,1473.86 v1(2150,1520) ; v1(2160,1210) 2185.39,1184.61 2185.39,1132.17 C5.2@2187.56,1130
  Top Layer w100: J7.2@2775,300 TP12.1@3000,300
  Signal Layer 2 w7.85: v1(2150,1520) NT6.1@2150,1540
  other v1: 1950,550 2070,550 2310,550 2790,550 2730,750 2121.26,880.63 2160.63,880.63 2200,880.63 2239.37,880.63 2278.74,880.63 1690,890 2121.26,920 2160.63,920 2200,920 2239.37,920 2278.74,920 2121.26,959.37 2160.63,959.37 2200,959.37 2239.37,959.37 2278.74,959.37 1630,1030 1820,1030 2770,1110 2610,1190 1400,1220 1590,1230
  other v2: 2120,1410 2180,1410 1610,1820 1740,1820 2560,1820 2690,1820 2175,1900 2125,2500
HDRV1_N: C4.2 Q1.4 U1.28 | length 667.4
  Top Layer w15: v1@2000,1291 1998,1293 v1(2000,1295) 2000,1142.44 C4.2@2012.44,1130 2012.44,1077.56 2033.66,1056.34 U1.28@2033.66,1032.2 ; v1(2010,1630) Q1.4@2010,1670
  Bottom Layer w12.5: v1(2000,1295) 2000,1310 1992.87,1317.13 1992.87,1612.87 v1(2010,1630)
HDRV1_P: RH1.1 U1.27 | length 223.1
  Top Layer w15: v1(1960,1160) RH1.1@1960,1202.44 ; v1(2050,1090) 2059.25,1080.75 U1.27@2059.25,1032.2
  Bottom Layer w15: v1(1960,1160) 1980,1160 v1(2050,1090)
HDRV2_N: C13.1 Q2.4 U1.18 | length 753.1
  Top Layer w12.5: U1.18@2289.57,1032.2 2291.25,1033.89 2291.25,1089.48 2307.56,1105.79 C13.1@2307.56,1130 2307.56,1167.56 2320,1180 v1(2320,1295) ; Q2.4@2368.39,1671.73 2368.39,1660.91 2380,1649.29 v1(2380,1630)
  Bottom Layer w12.5: v1(2320,1295) 2320,1300.37 2339.63,1320 2339.63,1561.56 2329.63,1571.56 2329.63,1616.26 2325.88,1620.01 2325.88,1639.99 2340.01,1654.12 2359.99,1654.12 2380,1634.12 v1(2380,1630)
HDRV2_P: RH2.2 U1.19 | length 212.9
  Top Layer w12.5: U1.19@2263.98,1032.2 v1@2263.98,1088.98 ; v1(2340,1165) 2345,1165 2360,1180 RH2.2@2360,1202.44
  Top Layer w15: v1@2263.98,1088.98 v1(2265,1090)
  Bottom Layer w12.5: v1(2265,1090) v1(2340,1165)
ISNS_CHG_N: NT8.1 U8.4 U8.5 | length 267.5
  Top Layer w7.87: U8.4@2713.97,1193.39 U8.5@2713.97,1209.14 2735.29,1209.14 2740.09,1213.94 2759.91,1213.94 2780,1193.85 v1(2780,1190)
  Bottom Layer w7.87: v1(2780,1190) 2788.57,1190 2811.45,1167.13 2917.87,1167.13 NT8.1@2935,1150
ISNS_CHG_P: NT7.1 U8.2 U8.3 | length 273.9
  Top Layer w7.87: U8.2@2690.36,1177.64 U8.3@2713.97,1177.64 2737.64,1177.64 v1(2750,1190)
  Bottom Layer w7.87: v1(2750,1190) 2750,1193.85 2770.09,1213.94 2789.91,1213.94 2818.85,1185 NT7.1@2935,1185
ISNS_IN_N: NT2.1 U3.4 U3.5 | length 328.3
  Top Layer w7.85: v1(1446.46,1320) 1469.38,1320 1472.43,1323.05 U3.5@1482.17,1323.05 U3.4@1497.92,1323.05
  Bottom Layer w10: v1(1446.46,1320) 1446.46,1356.46 1450,1360 1450,1563.74 1460,1573.74 NT2.1@1460,1590
ISNS_IN_P: NT1.2 U3.2 U3.3 | length 452.7
  Top Layer w7.85: U3.2@1513.67,1299.5 U3.3@1513.67,1323.05 1526.95,1323.05 1530,1320 ; 1529.43,1319.43 1530,1320 ; v1(1550,1320) 1530,1320
  Bottom Layer w10: NT1.2@1430,1550 1430,1370 1420,1360 1420,1310 1435,1295 1456.82,1295 1481.82,1320 v1(1550,1320)
ISNS_OUT_N: NT4.1 R18.1 | length 1065.3
  Top Layer w20: R18.1@2557.56,770 v1(2595,770)
  Bottom Layer w10: v1@2600,770 v1(2595,770) 2620,795 2620,941.72 2692.87,1014.59 2692.87,1280 2882.87,1470 2882.87,1575.79 2940,1632.91 NT4.1@2940,1650
ISNS_OUT_P: NT3.1 R22.1 | length 817.2
  Top Layer w20: R22.1@2557.56,830 v1(2595,830)
  Bottom Layer w10: v1(2595,830) 2595,945 2672.87,1022.87 2672.87,1289.88 2860,1477.01 NT3.1@2860,1500
LDRV1: RL1.1 U1.25 | length 174.6
  Top Layer w12.5: RL1.1@2100,1202.44 2100,1100 2110.43,1089.57 U1.25@2110.43,1032.2
LDRV2: RL2.2 U1.21 | length 172.7
  Top Layer w12.5: U1.21@2212.8,1032.2 2212.8,1092.8 2220,1100 RL2.2@2220,1201.95
MODE: R6.1 R12.2 U1.4 | length 399.2
  Top Layer w12.5: R12.2@1890,647.56 1890,680 1910.37,700.37 2060,700.37 2110.43,750.81 U1.4@2110.43,807.8
  Top Layer w25: R6.1@1830,647.56 R12.2@1890,647.56
NetC3_1: C3.1 TP6.1 | length 379.4
  Top Layer w25: TP6.1@1800,300 2010,510 C3.1@2010,592.44
NetC11_1: C11.1 R11.1 | length 60
  Top Layer w20: R11.1@2370,592.44 C11.1@2430,592.44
